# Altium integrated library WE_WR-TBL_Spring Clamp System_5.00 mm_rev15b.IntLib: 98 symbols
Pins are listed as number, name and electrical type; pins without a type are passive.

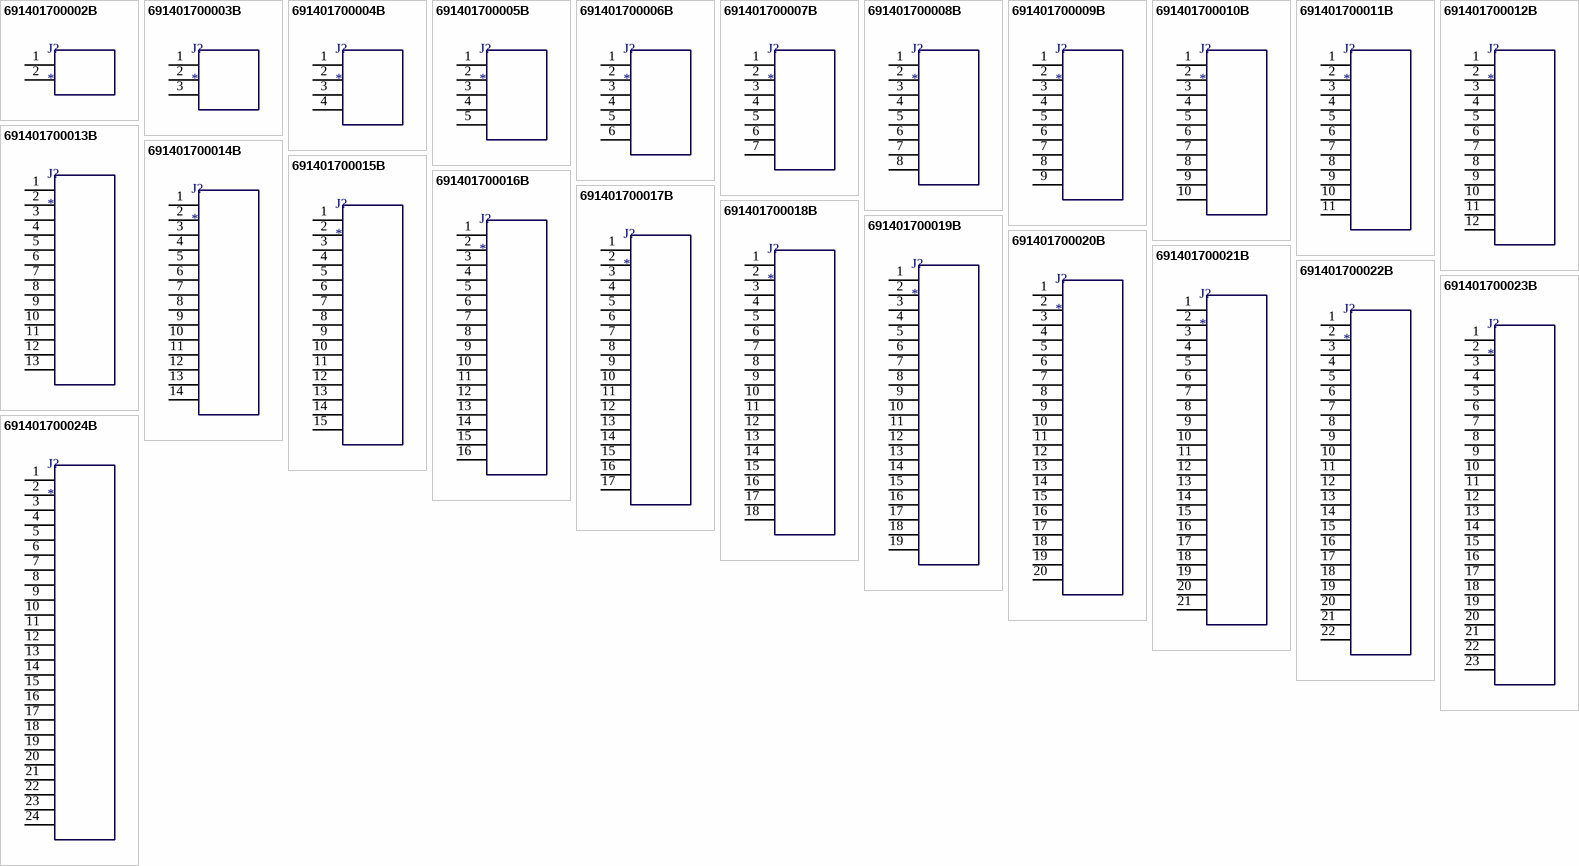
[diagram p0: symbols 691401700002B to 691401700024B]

## 691401700002B
designator J?
WR-TBL Screwless Entry Vertical,Serie 401 B - 5.00 mm; Manufacturer: Würth Elektronik eiSos GmbH; partNo: 691401700002B; ComponentLink1 Description: Manufacturer; ComponentLink2 Description: Datasheet; NoPins: 4
footprint 691401700002B
pins: 1  , 2  

## 691401700003B
designator J?
WR-TBL Screwless Entry Vertical,Serie 401 B - 5.00 mm; Manufacturer: Würth Elektronik eiSos GmbH; partNo: 691401700003B; ComponentLink1 Description: Manufacturer; ComponentLink2 Description: Datasheet; NoPins: 6
footprint 691401700003B
pins: 1  , 2  , 3  

## 691401700004B
designator J?
WR-TBL Screwless Entry Vertical,Serie 401 B - 5.00 mm; Manufacturer: Würth Elektronik eiSos GmbH; partNo: 691401700004B; ComponentLink1 Description: Manufacturer; ComponentLink2 Description: Datasheet; NoPins: 8
footprint 691401700004B
pins: 1  , 2  , 3  , 4  

## 691401700005B
designator J?
WR-TBL Screwless Entry Vertical,Serie 401 B - 5.00 mm; Manufacturer: Würth Elektronik eiSos GmbH; partNo: 691401700005B; ComponentLink1 Description: Manufacturer; ComponentLink2 Description: Datasheet; NoPins: 10
footprint 691401700005B
pins: 1  , 2  , 3  , 4  , 5  

## 691401700006B
designator J?
WR-TBL Screwless Entry Vertical,Serie 401 B - 5.00 mm; Manufacturer: Würth Elektronik eiSos GmbH; partNo: 691401700006B; ComponentLink1 Description: Manufacturer; ComponentLink2 Description: Datasheet; NoPins: 12
footprint 691401700006B
pins: 1  , 2  , 3  , 4  , 5  , 6  

## 691401700007B
designator J?
WR-TBL Screwless Entry Vertical,Serie 401 B - 5.00 mm; Manufacturer: Würth Elektronik eiSos GmbH; partNo: 691401700007B; ComponentLink1 Description: Manufacturer; ComponentLink2 Description: Datasheet; NoPins: 14
footprint 691401700007B
pins: 1  , 2  , 3  , 4  , 5  , 6  , 7  

## 691401700008B
designator J?
WR-TBL Screwless Entry Vertical,Serie 401 B - 5.00 mm; Manufacturer: Würth Elektronik eiSos GmbH; partNo: 691401700008B; ComponentLink1 Description: Manufacturer; ComponentLink2 Description: Datasheet; NoPins: 16
footprint 691401700008B
pins: 1  , 2  , 3  , 4  , 5  , 6  , 7  , 8  

## 691401700009B
designator J?
WR-TBL Screwless Entry Vertical,Serie 401 B - 5.00 mm; Manufacturer: Würth Elektronik eiSos GmbH; partNo: 691401700009B; ComponentLink1 Description: Manufacturer; ComponentLink2 Description: Datasheet; NoPins: 18
footprint 691401700009B
pins: 1  , 2  , 3  , 4  , 5  , 6  , 7  , 8  , 9  

## 691401700010B
designator J?
WR-TBL Screwless Entry Vertical,Serie 401 B - 5.00 mm; Manufacturer: Würth Elektronik eiSos GmbH; partNo: 691401700010B; ComponentLink1 Description: Manufacturer; ComponentLink2 Description: Datasheet; NoPins: 20
footprint 691401700010B
pins: 1  , 2  , 3  , 4  , 5  , 6  , 7  , 8  , 9  , 10  

## 691401700011B
designator J?
WR-TBL Screwless Entry Vertical,Serie 401 B - 5.00 mm; Manufacturer: Würth Elektronik eiSos GmbH; partNo: 691401700011B; ComponentLink1 Description: Manufacturer; ComponentLink2 Description: Datasheet; NoPins: 22
footprint 691401700011B
pins: 1  , 2  , 3  , 4  , 5  , 6  , 7  , 8  , 9  , 10  , 11  

## 691401700012B
designator J?
WR-TBL Screwless Entry Vertical,Serie 401 B - 5.00 mm; Manufacturer: Würth Elektronik eiSos GmbH; partNo: 691401700012B; ComponentLink1 Description: Manufacturer; ComponentLink2 Description: Datasheet; NoPins: 24
footprint 691401700012B
pins: 1  , 2  , 3  , 4  , 5  , 6  , 7  , 8  , 9  , 10  , 11  , 12  

## 691401700013B
designator J?
WR-TBL Screwless Entry Vertical,Serie 401 B - 5.00 mm; Manufacturer: Würth Elektronik eiSos GmbH; partNo: 691401700013B; ComponentLink1 Description: Manufacturer; ComponentLink2 Description: Datasheet; NoPins: 26
footprint 691401700013B
pins: 1  , 2  , 3  , 4  , 5  , 6  , 7  , 8  , 9  , 10  , 11  , 12  , 13  

## 691401700014B
designator J?
WR-TBL Screwless Entry Vertical,Serie 401 B - 5.00 mm; Manufacturer: Würth Elektronik eiSos GmbH; partNo: 691401700014B; ComponentLink1 Description: Manufacturer; ComponentLink2 Description: Datasheet; NoPins: 28
footprint 691401700014B
pins: 1  , 2  , 3  , 4  , 5  , 6  , 7  , 8  , 9  , 10  , 11  , 12  , 13  , 14  

## 691401700015B
designator J?
WR-TBL Screwless Entry Vertical,Serie 401 B - 5.00 mm; Manufacturer: Würth Elektronik eiSos GmbH; partNo: 691401700015B; ComponentLink1 Description: Manufacturer; ComponentLink2 Description: Datasheet; NoPins: 30
footprint 691401700015B
pins: 1  , 2  , 3  , 4  , 5  , 6  , 7  , 8  , 9  , 10  , 11  , 12  , 13  , 14  , 15  

## 691401700016B
designator J?
WR-TBL Screwless Entry Vertical,Serie 401 B - 5.00 mm; Manufacturer: Würth Elektronik eiSos GmbH; partNo: 691401700016B; ComponentLink1 Description: Manufacturer; ComponentLink2 Description: Datasheet; NoPins: 32
footprint 691401700016B
pins: 1  , 2  , 3  , 4  , 5  , 6  , 7  , 8  , 9  , 10  , 11  , 12  , 13  , 14  , 15  , 16  

## 691401700017B
designator J?
WR-TBL Screwless Entry Vertical,Serie 401 B - 5.00 mm; Manufacturer: Würth Elektronik eiSos GmbH; partNo: 691401700017B; ComponentLink1 Description: Manufacturer; ComponentLink2 Description: Datasheet; NoPins: 34
footprint 691401700017B
pins: 1  , 2  , 3  , 4  , 5  , 6  , 7  , 8  , 9  , 10  , 11  , 12  , 13  , 14  , 15  , 16  , 17  

## 691401700018B
designator J?
WR-TBL Screwless Entry Vertical,Serie 401 B - 5.00 mm; Manufacturer: Würth Elektronik eiSos GmbH; partNo: 691401700018B; ComponentLink1 Description: Manufacturer; ComponentLink2 Description: Datasheet; NoPins: 36
footprint 691401700018B
pins: 1  , 2  , 3  , 4  , 5  , 6  , 7  , 8  , 9  , 10  , 11  , 12  , 13  , 14  , 15  , 16  , 17  , 18  

## 691401700019B
designator J?
WR-TBL Screwless Entry Vertical,Serie 401 B - 5.00 mm; Manufacturer: Würth Elektronik eiSos GmbH; partNo: 691401700019B; ComponentLink1 Description: Manufacturer; ComponentLink2 Description: Datasheet; NoPins: 38
footprint 691401700019B
pins: 1  , 2  , 3  , 4  , 5  , 6  , 7  , 8  , 9  , 10  , 11  , 12  , 13  , 14  , 15  , 16  , 17  , 18  , 19  

## 691401700020B
designator J?
WR-TBL Screwless Entry Vertical,Serie 401 B - 5.00 mm; Manufacturer: Würth Elektronik eiSos GmbH; partNo: 691401700020B; ComponentLink1 Description: Manufacturer; ComponentLink2 Description: Datasheet; NoPins: 40
footprint 691401700020B
pins: 1  , 2  , 3  , 4  , 5  , 6  , 7  , 8  , 9  , 10  , 11  , 12  , 13  , 14  , 15  , 16  , 17  , 18  , 19  , 20  

## 691401700021B
designator J?
WR-TBL Screwless Entry Vertical,Serie 401 B - 5.00 mm; Manufacturer: Würth Elektronik eiSos GmbH; partNo: 691401700021B; ComponentLink1 Description: Manufacturer; ComponentLink2 Description: Datasheet; NoPins: 42
footprint 691401700021B
pins: 1  , 2  , 3  , 4  , 5  , 6  , 7  , 8  , 9  , 10  , 11  , 12  , 13  , 14  , 15  , 16  , 17  , 18  , 19  , 20  , 21  

## 691401700022B
designator J?
WR-TBL Screwless Entry Vertical,Serie 401 B - 5.00 mm; Manufacturer: Würth Elektronik eiSos GmbH; partNo: 691401700022B; ComponentLink1 Description: Manufacturer; ComponentLink2 Description: Datasheet; NoPins: 44
footprint 691401700022B
pins: 1  , 2  , 3  , 4  , 5  , 6  , 7  , 8  , 9  , 10  , 11  , 12  , 13  , 14  , 15  , 16  , 17  , 18  , 19  , 20  , 21  , 22  

## 691401700023B
designator J?
WR-TBL Screwless Entry Vertical,Serie 401 B - 5.00 mm; Manufacturer: Würth Elektronik eiSos GmbH; partNo: 691401700023B; ComponentLink1 Description: Manufacturer; ComponentLink2 Description: Datasheet; NoPins: 46
footprint 691401700023B
pins: 1  , 2  , 3  , 4  , 5  , 6  , 7  , 8  , 9  , 10  , 11  , 12  , 13  , 14  , 15  , 16  , 17  , 18  , 19  , 20  , 21  , 22  , 23  

## 691401700024B
designator J?
WR-TBL Screwless Entry Vertical,Serie 401 B - 5.00 mm; Manufacturer: Würth Elektronik eiSos GmbH; partNo: 691401700024B; ComponentLink1 Description: Manufacturer; ComponentLink2 Description: Datasheet; NoPins: 48
footprint 691401700024B
pins: 1  , 2  , 3  , 4  , 5  , 6  , 7  , 8  , 9  , 10  , 11  , 12  , 13  , 14  , 15  , 16  , 17  , 18  , 19  , 20  , 21  , 22  , 23  , 24  


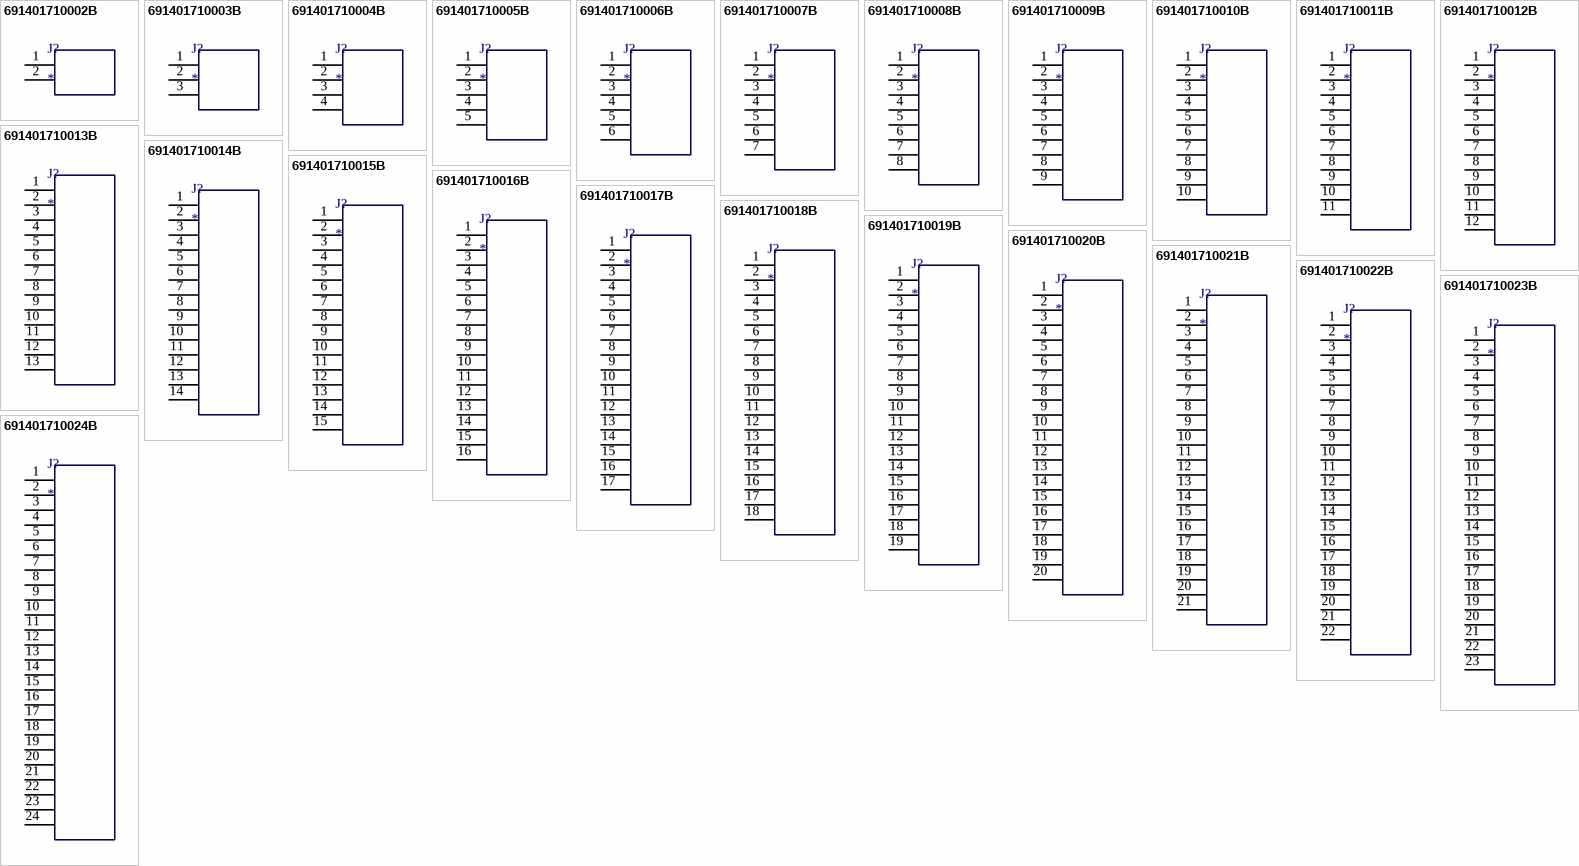
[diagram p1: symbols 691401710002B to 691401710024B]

## 691401710002B
designator J?
WR-TBL Screwless Entry Horizontal,Serie 401 B - 5.00 mm; Manufacturer: Würth Elektronik eiSos GmbH; partNo: 691401710002B; ComponentLink1 Description: Manufacturer; ComponentLink2 Description: Datasheet; NoPins: 4
footprint 691401710002B
pins: 1  , 2  

## 691401710003B
designator J?
WR-TBL Screwless Entry Horizontal,Serie 401 B - 5.00 mm; Manufacturer: Würth Elektronik eiSos GmbH; partNo: 691401710003B; ComponentLink1 Description: Manufacturer; ComponentLink2 Description: Datasheet; NoPins: 6
footprint 691401710003B
pins: 1  , 2  , 3  

## 691401710004B
designator J?
WR-TBL Screwless Entry Horizontal,Serie 401 B - 5.00 mm; Manufacturer: Würth Elektronik eiSos GmbH; partNo: 691401710004B; ComponentLink1 Description: Manufacturer; ComponentLink2 Description: Datasheet; NoPins: 8
footprint 691401710004B
pins: 1  , 2  , 3  , 4  

## 691401710005B
designator J?
WR-TBL Screwless Entry Horizontal,Serie 401 B - 5.00 mm; Manufacturer: Würth Elektronik eiSos GmbH; partNo: 691401710005B; ComponentLink1 Description: Manufacturer; ComponentLink2 Description: Datasheet; NoPins: 10
footprint 691401710005B
pins: 1  , 2  , 3  , 4  , 5  

## 691401710006B
designator J?
WR-TBL Screwless Entry Horizontal,Serie 401 B - 5.00 mm; Manufacturer: Würth Elektronik eiSos GmbH; partNo: 691401710006B; ComponentLink1 Description: Manufacturer; ComponentLink2 Description: Datasheet; NoPins: 12
footprint 691401710006B
pins: 1  , 2  , 3  , 4  , 5  , 6  

## 691401710007B
designator J?
WR-TBL Screwless Entry Horizontal,Serie 401 B - 5.00 mm; Manufacturer: Würth Elektronik eiSos GmbH; partNo: 691401710007B; ComponentLink1 Description: Manufacturer; ComponentLink2 Description: Datasheet; NoPins: 14
footprint 691401710007B
pins: 1  , 2  , 3  , 4  , 5  , 6  , 7  

## 691401710008B
designator J?
WR-TBL Screwless Entry Horizontal,Serie 401 B - 5.00 mm; Manufacturer: Würth Elektronik eiSos GmbH; partNo: 691401710008B; ComponentLink1 Description: Manufacturer; ComponentLink2 Description: Datasheet; NoPins: 16
footprint 691401710008B
pins: 1  , 2  , 3  , 4  , 5  , 6  , 7  , 8  

## 691401710009B
designator J?
WR-TBL Screwless Entry Horizontal,Serie 401 B - 5.00 mm; Manufacturer: Würth Elektronik eiSos GmbH; partNo: 691401710009B; ComponentLink1 Description: Manufacturer; ComponentLink2 Description: Datasheet; NoPins: 18
footprint 691401710009B
pins: 1  , 2  , 3  , 4  , 5  , 6  , 7  , 8  , 9  

## 691401710010B
designator J?
WR-TBL Screwless Entry Horizontal,Serie 401 B - 5.00 mm; Manufacturer: Würth Elektronik eiSos GmbH; partNo: 691401710010B; ComponentLink1 Description: Manufacturer; ComponentLink2 Description: Datasheet; NoPins: 20
footprint 691401710010B
pins: 1  , 2  , 3  , 4  , 5  , 6  , 7  , 8  , 9  , 10  

## 691401710011B
designator J?
WR-TBL Screwless Entry Horizontal,Serie 401 B - 5.00 mm; Manufacturer: Würth Elektronik eiSos GmbH; partNo: 691401710011B; ComponentLink1 Description: Manufacturer; ComponentLink2 Description: Datasheet; NoPins: 22
footprint 691401710011B
pins: 1  , 2  , 3  , 4  , 5  , 6  , 7  , 8  , 9  , 10  , 11  

## 691401710012B
designator J?
WR-TBL Screwless Entry Horizontal,Serie 401 B - 5.00 mm; Manufacturer: Würth Elektronik eiSos GmbH; partNo: 691401710012B; ComponentLink1 Description: Manufacturer; ComponentLink2 Description: Datasheet; NoPins: 24
footprint 691401710012B
pins: 1  , 2  , 3  , 4  , 5  , 6  , 7  , 8  , 9  , 10  , 11  , 12  

## 691401710013B
designator J?
WR-TBL Screwless Entry Horizontal,Serie 401 B - 5.00 mm; Manufacturer: Würth Elektronik eiSos GmbH; partNo: 691401710013B; ComponentLink1 Description: Manufacturer; ComponentLink2 Description: Datasheet; NoPins: 26
footprint 691401710013B
pins: 1  , 2  , 3  , 4  , 5  , 6  , 7  , 8  , 9  , 10  , 11  , 12  , 13  

## 691401710014B
designator J?
WR-TBL Screwless Entry Horizontal,Serie 401 B - 5.00 mm; Manufacturer: Würth Elektronik eiSos GmbH; partNo: 691401710014B; ComponentLink1 Description: Manufacturer; ComponentLink2 Description: Datasheet; NoPins: 28
footprint 691401710014B
pins: 1  , 2  , 3  , 4  , 5  , 6  , 7  , 8  , 9  , 10  , 11  , 12  , 13  , 14  

## 691401710015B
designator J?
WR-TBL Screwless Entry Horizontal,Serie 401 B - 5.00 mm; Manufacturer: Würth Elektronik eiSos GmbH; partNo: 691401710015B; ComponentLink1 Description: Manufacturer; ComponentLink2 Description: Datasheet; NoPins: 30
footprint 691401710015B
pins: 1  , 2  , 3  , 4  , 5  , 6  , 7  , 8  , 9  , 10  , 11  , 12  , 13  , 14  , 15  

## 691401710016B
designator J?
WR-TBL Screwless Entry Horizontal,Serie 401 B - 5.00 mm; Manufacturer: Würth Elektronik eiSos GmbH; partNo: 691401710016B; ComponentLink1 Description: Manufacturer; ComponentLink2 Description: Datasheet; NoPins: 32
footprint 691401710016B
pins: 1  , 2  , 3  , 4  , 5  , 6  , 7  , 8  , 9  , 10  , 11  , 12  , 13  , 14  , 15  , 16  

## 691401710017B
designator J?
WR-TBL Screwless Entry Horizontal,Serie 401 B - 5.00 mm; Manufacturer: Würth Elektronik eiSos GmbH; partNo: 691401710017B; ComponentLink1 Description: Manufacturer; ComponentLink2 Description: Datasheet; NoPins: 34
footprint 691401710017B
pins: 1  , 2  , 3  , 4  , 5  , 6  , 7  , 8  , 9  , 10  , 11  , 12  , 13  , 14  , 15  , 16  , 17  

## 691401710018B
designator J?
WR-TBL Screwless Entry Horizontal,Serie 401 B - 5.00 mm; Manufacturer: Würth Elektronik eiSos GmbH; partNo: 691401710018B; ComponentLink1 Description: Manufacturer; ComponentLink2 Description: Datasheet; NoPins: 36
footprint 691401710018B
pins: 1  , 2  , 3  , 4  , 5  , 6  , 7  , 8  , 9  , 10  , 11  , 12  , 13  , 14  , 15  , 16  , 17  , 18  

## 691401710019B
designator J?
WR-TBL Screwless Entry Horizontal,Serie 401 B - 5.00 mm; Manufacturer: Würth Elektronik eiSos GmbH; partNo: 691401710019B; ComponentLink1 Description: Manufacturer; ComponentLink2 Description: Datasheet; NoPins: 38
footprint 691401710019B
pins: 1  , 2  , 3  , 4  , 5  , 6  , 7  , 8  , 9  , 10  , 11  , 12  , 13  , 14  , 15  , 16  , 17  , 18  , 19  

## 691401710020B
designator J?
WR-TBL Screwless Entry Horizontal,Serie 401 B - 5.00 mm; Manufacturer: Würth Elektronik eiSos GmbH; partNo: 691401710020B; ComponentLink1 Description: Manufacturer; ComponentLink2 Description: Datasheet; NoPins: 40
footprint 691401710020B
pins: 1  , 2  , 3  , 4  , 5  , 6  , 7  , 8  , 9  , 10  , 11  , 12  , 13  , 14  , 15  , 16  , 17  , 18  , 19  , 20  

## 691401710021B
designator J?
WR-TBL Screwless Entry Horizontal,Serie 401 B - 5.00 mm; Manufacturer: Würth Elektronik eiSos GmbH; partNo: 691401710021B; ComponentLink1 Description: Manufacturer; ComponentLink2 Description: Datasheet; NoPins: 42
footprint 691401710021B
pins: 1  , 2  , 3  , 4  , 5  , 6  , 7  , 8  , 9  , 10  , 11  , 12  , 13  , 14  , 15  , 16  , 17  , 18  , 19  , 20  , 21  

## 691401710022B
designator J?
WR-TBL Screwless Entry Horizontal,Serie 401 B - 5.00 mm; Manufacturer: Würth Elektronik eiSos GmbH; partNo: 691401710022B; ComponentLink1 Description: Manufacturer; ComponentLink2 Description: Datasheet; NoPins: 44
footprint 691401710022B
pins: 1  , 2  , 3  , 4  , 5  , 6  , 7  , 8  , 9  , 10  , 11  , 12  , 13  , 14  , 15  , 16  , 17  , 18  , 19  , 20  , 21  , 22  

## 691401710023B
designator J?
WR-TBL Screwless Entry Horizontal,Serie 401 B - 5.00 mm; Manufacturer: Würth Elektronik eiSos GmbH; partNo: 691401710023B; ComponentLink1 Description: Manufacturer; ComponentLink2 Description: Datasheet; NoPins: 46
footprint 691401710023B
pins: 1  , 2  , 3  , 4  , 5  , 6  , 7  , 8  , 9  , 10  , 11  , 12  , 13  , 14  , 15  , 16  , 17  , 18  , 19  , 20  , 21  , 22  , 23  

## 691401710024B
designator J?
WR-TBL Screwless Entry Horizontal,Serie 401 B - 5.00 mm; Manufacturer: Würth Elektronik eiSos GmbH; partNo: 691401710024B; ComponentLink1 Description: Manufacturer; ComponentLink2 Description: Datasheet; NoPins: 48
footprint 691401710024B
pins: 1  , 2  , 3  , 4  , 5  , 6  , 7  , 8  , 9  , 10  , 11  , 12  , 13  , 14  , 15  , 16  , 17  , 18  , 19  , 20  , 21  , 22  , 23  , 24  


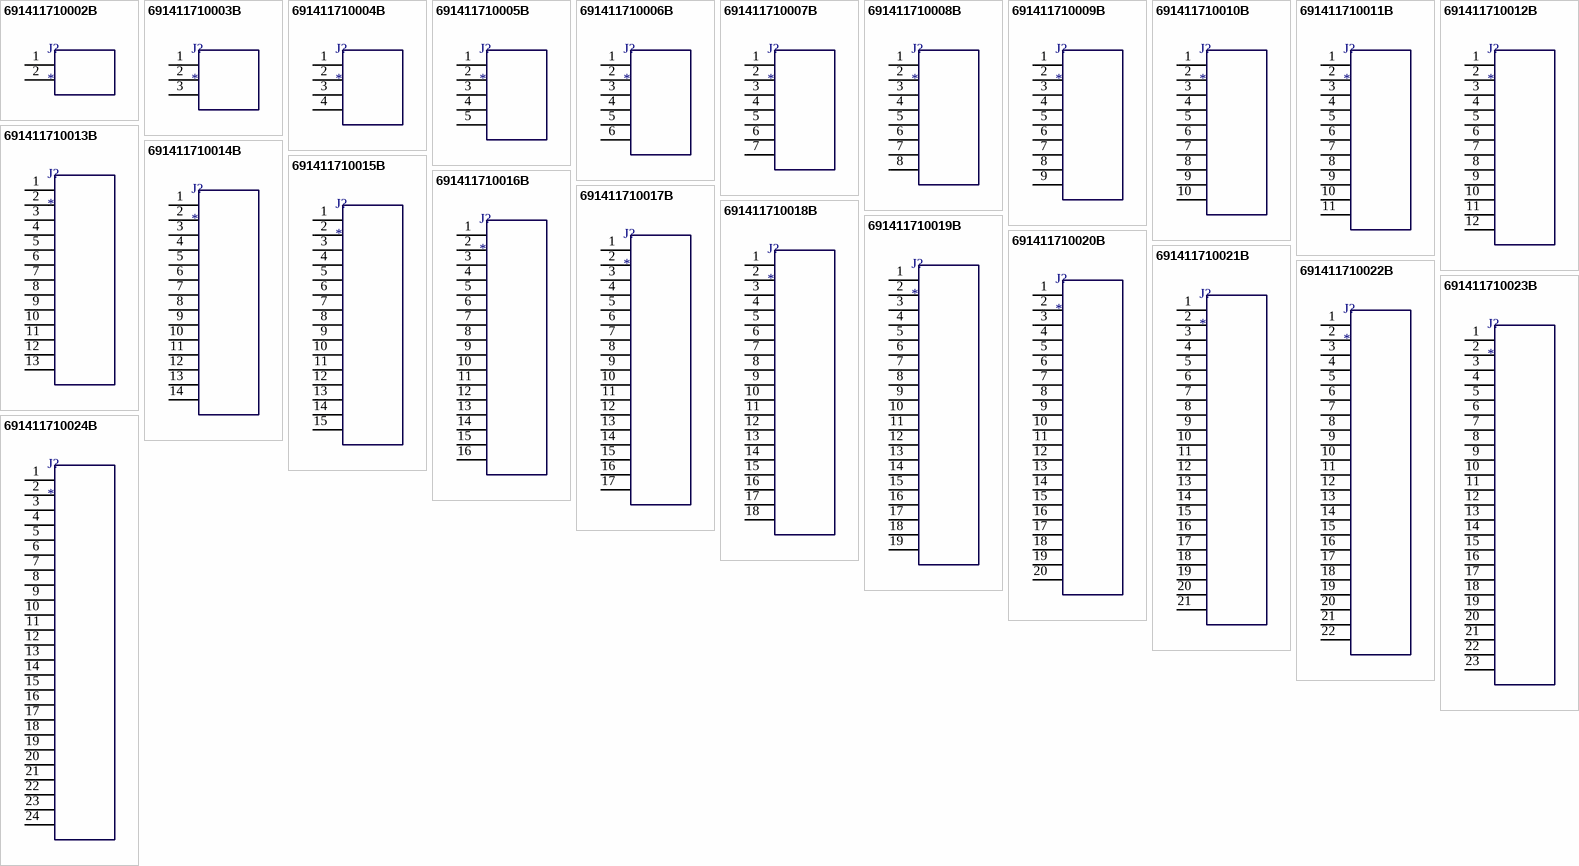
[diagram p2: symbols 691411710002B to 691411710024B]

## 691411710002B
designator J?
WR-TBL Screwless Entry Horizontal, Serie 411 B - 5.00 mm; Manufacturer: Würth Elektronik eiSos GmbH; partNo: 691411710002B; ComponentLink1 Description: Manufacturer; ComponentLink2 Description: Datasheet; NoPins: 4
footprint 691411710002B
pins: 1  , 2  

## 691411710003B
designator J?
WR-TBL Screwless Entry Horizontal, Serie 411 B - 5.00 mm; Manufacturer: Würth Elektronik eiSos GmbH; partNo: 691411710003B; ComponentLink1 Description: Manufacturer; ComponentLink2 Description: Datasheet; NoPins: 6
footprint 691411710003B
pins: 1  , 2  , 3  

## 691411710004B
designator J?
WR-TBL Screwless Entry Horizontal, Serie 411 B - 5.00 mm; Manufacturer: Würth Elektronik eiSos GmbH; partNo: 691411710004B; ComponentLink1 Description: Manufacturer; ComponentLink2 Description: Datasheet; NoPins: 8
footprint 691411710004B
pins: 1  , 2  , 3  , 4  

## 691411710005B
designator J?
WR-TBL Screwless Entry Horizontal, Serie 411 B - 5.00 mm; Manufacturer: Würth Elektronik eiSos GmbH; partNo: 691411710005B; ComponentLink1 Description: Manufacturer; ComponentLink2 Description: Datasheet; NoPins: 10
footprint 691411710005B
pins: 1  , 2  , 3  , 4  , 5  

## 691411710006B
designator J?
WR-TBL Screwless Entry Horizontal, Serie 411 B - 5.00 mm; Manufacturer: Würth Elektronik eiSos GmbH; partNo: 691411710006B; ComponentLink1 Description: Manufacturer; ComponentLink2 Description: Datasheet; NoPins: 12
footprint 691411710006B
pins: 1  , 2  , 3  , 4  , 5  , 6  

## 691411710007B
designator J?
WR-TBL Screwless Entry Horizontal, Serie 411 B - 5.00 mm; Manufacturer: Würth Elektronik eiSos GmbH; partNo: 691411710007B; ComponentLink1 Description: Manufacturer; ComponentLink2 Description: Datasheet; NoPins: 14
footprint 691411710007B
pins: 1  , 2  , 3  , 4  , 5  , 6  , 7  

## 691411710008B
designator J?
WR-TBL Screwless Entry Horizontal, Serie 411 B - 5.00 mm; Manufacturer: Würth Elektronik eiSos GmbH; partNo: 691411710008B; ComponentLink1 Description: Manufacturer; ComponentLink2 Description: Datasheet; NoPins: 16
footprint 691411710008B
pins: 1  , 2  , 3  , 4  , 5  , 6  , 7  , 8  

## 691411710009B
designator J?
WR-TBL Screwless Entry Horizontal, Serie 411 B - 5.00 mm; Manufacturer: Würth Elektronik eiSos GmbH; partNo: 691411710009B; ComponentLink1 Description: Manufacturer; ComponentLink2 Description: Datasheet; NoPins: 18
footprint 691411710009B
pins: 1  , 2  , 3  , 4  , 5  , 6  , 7  , 8  , 9  

## 691411710010B
designator J?
WR-TBL Screwless Entry Horizontal, Serie 411 B - 5.00 mm; Manufacturer: Würth Elektronik eiSos GmbH; partNo: 691411710010B; ComponentLink1 Description: Manufacturer; ComponentLink2 Description: Datasheet; NoPins: 20
footprint 691411710010B
pins: 1  , 2  , 3  , 4  , 5  , 6  , 7  , 8  , 9  , 10  

## 691411710011B
designator J?
WR-TBL Screwless Entry Horizontal, Serie 411 B - 5.00 mm; Manufacturer: Würth Elektronik eiSos GmbH; partNo: 691411710011B; ComponentLink1 Description: Manufacturer; ComponentLink2 Description: Datasheet; NoPins: 22
footprint 691411710011B
pins: 1  , 2  , 3  , 4  , 5  , 6  , 7  , 8  , 9  , 10  , 11  

## 691411710012B
designator J?
WR-TBL Screwless Entry Horizontal, Serie 411 B - 5.00 mm; Manufacturer: Würth Elektronik eiSos GmbH; partNo: 691411710012B; ComponentLink1 Description: Manufacturer; ComponentLink2 Description: Datasheet; NoPins: 24
footprint 691411710012B
pins: 1  , 2  , 3  , 4  , 5  , 6  , 7  , 8  , 9  , 10  , 11  , 12  

## 691411710013B
designator J?
WR-TBL Screwless Entry Horizontal, Serie 411 B - 5.00 mm; Manufacturer: Würth Elektronik eiSos GmbH; partNo: 691411710013B; ComponentLink1 Description: Manufacturer; ComponentLink2 Description: Datasheet; NoPins: 26
footprint 691411710013B
pins: 1  , 2  , 3  , 4  , 5  , 6  , 7  , 8  , 9  , 10  , 11  , 12  , 13  

## 691411710014B
designator J?
WR-TBL Screwless Entry Horizontal, Serie 411 B - 5.00 mm; Manufacturer: Würth Elektronik eiSos GmbH; partNo: 691411710014B; ComponentLink1 Description: Manufacturer; ComponentLink2 Description: Datasheet; NoPins: 28
footprint 691411710014B
pins: 1  , 2  , 3  , 4  , 5  , 6  , 7  , 8  , 9  , 10  , 11  , 12  , 13  , 14  

## 691411710015B
designator J?
WR-TBL Screwless Entry Horizontal, Serie 411 B - 5.00 mm; Manufacturer: Würth Elektronik eiSos GmbH; partNo: 691411710015B; ComponentLink1 Description: Manufacturer; ComponentLink2 Description: Datasheet; NoPins: 30
footprint 691411710015B
pins: 1  , 2  , 3  , 4  , 5  , 6  , 7  , 8  , 9  , 10  , 11  , 12  , 13  , 14  , 15  

## 691411710016B
designator J?
WR-TBL Screwless Entry Horizontal, Serie 411 B - 5.00 mm; Manufacturer: Würth Elektronik eiSos GmbH; partNo: 691411710016B; ComponentLink1 Description: Manufacturer; ComponentLink2 Description: Datasheet; NoPins: 32
footprint 691411710016B
pins: 1  , 2  , 3  , 4  , 5  , 6  , 7  , 8  , 9  , 10  , 11  , 12  , 13  , 14  , 15  , 16  

## 691411710017B
designator J?
WR-TBL Screwless Entry Horizontal, Serie 411 B - 5.00 mm; Manufacturer: Würth Elektronik eiSos GmbH; partNo: 691411710017B; ComponentLink1 Description: Manufacturer; ComponentLink2 Description: Datasheet; NoPins: 34
footprint 691411710017B
pins: 1  , 2  , 3  , 4  , 5  , 6  , 7  , 8  , 9  , 10  , 11  , 12  , 13  , 14  , 15  , 16  , 17  

## 691411710018B
designator J?
WR-TBL Screwless Entry Horizontal, Serie 411 B - 5.00 mm; Manufacturer: Würth Elektronik eiSos GmbH; partNo: 691411710018B; ComponentLink1 Description: Manufacturer; ComponentLink2 Description: Datasheet; NoPins: 36
footprint 691411710018B
pins: 1  , 2  , 3  , 4  , 5  , 6  , 7  , 8  , 9  , 10  , 11  , 12  , 13  , 14  , 15  , 16  , 17  , 18  

## 691411710019B
designator J?
WR-TBL Screwless Entry Horizontal, Serie 411 B - 5.00 mm; Manufacturer: Würth Elektronik eiSos GmbH; partNo: 691411710019B; ComponentLink1 Description: Manufacturer; ComponentLink2 Description: Datasheet; NoPins: 38
footprint 691411710019B
pins: 1  , 2  , 3  , 4  , 5  , 6  , 7  , 8  , 9  , 10  , 11  , 12  , 13  , 14  , 15  , 16  , 17  , 18  , 19  

## 691411710020B
designator J?
WR-TBL Screwless Entry Horizontal, Serie 411 B - 5.00 mm; Manufacturer: Würth Elektronik eiSos GmbH; partNo: 691411710020B; ComponentLink1 Description: Manufacturer; ComponentLink2 Description: Datasheet; NoPins: 40
footprint 691411710020B
pins: 1  , 2  , 3  , 4  , 5  , 6  , 7  , 8  , 9  , 10  , 11  , 12  , 13  , 14  , 15  , 16  , 17  , 18  , 19  , 20  

## 691411710021B
designator J?
WR-TBL Screwless Entry Horizontal, Serie 411 B - 5.00 mm; Manufacturer: Würth Elektronik eiSos GmbH; partNo: 691411710021B; ComponentLink1 Description: Manufacturer; ComponentLink2 Description: Datasheet; NoPins: 42
footprint 691411710021B
pins: 1  , 2  , 3  , 4  , 5  , 6  , 7  , 8  , 9  , 10  , 11  , 12  , 13  , 14  , 15  , 16  , 17  , 18  , 19  , 20  , 21  

## 691411710022B
designator J?
WR-TBL Screwless Entry Horizontal, Serie 411 B - 5.00 mm; Manufacturer: Würth Elektronik eiSos GmbH; partNo: 691411710022B; ComponentLink1 Description: Manufacturer; ComponentLink2 Description: Datasheet; NoPins: 44
footprint 691411710022B
pins: 1  , 2  , 3  , 4  , 5  , 6  , 7  , 8  , 9  , 10  , 11  , 12  , 13  , 14  , 15  , 16  , 17  , 18  , 19  , 20  , 21  , 22  

## 691411710023B
designator J?
WR-TBL Screwless Entry Horizontal, Serie 411 B - 5.00 mm; Manufacturer: Würth Elektronik eiSos GmbH; partNo: 691411710023B; ComponentLink1 Description: Manufacturer; ComponentLink2 Description: Datasheet; NoPins: 46
footprint 691411710023B
pins: 1  , 2  , 3  , 4  , 5  , 6  , 7  , 8  , 9  , 10  , 11  , 12  , 13  , 14  , 15  , 16  , 17  , 18  , 19  , 20  , 21  , 22  , 23  

## 691411710024B
designator J?
WR-TBL Screwless Entry Horizontal, Serie 411 B - 5.00 mm; Manufacturer: Würth Elektronik eiSos GmbH; partNo: 691411710024B; ComponentLink1 Description: Manufacturer; ComponentLink2 Description: Datasheet; NoPins: 48
footprint 691411710024B
pins: 1  , 2  , 3  , 4  , 5  , 6  , 7  , 8  , 9  , 10  , 11  , 12  , 13  , 14  , 15  , 16  , 17  , 18  , 19  , 20  , 21  , 22  , 23  , 24  


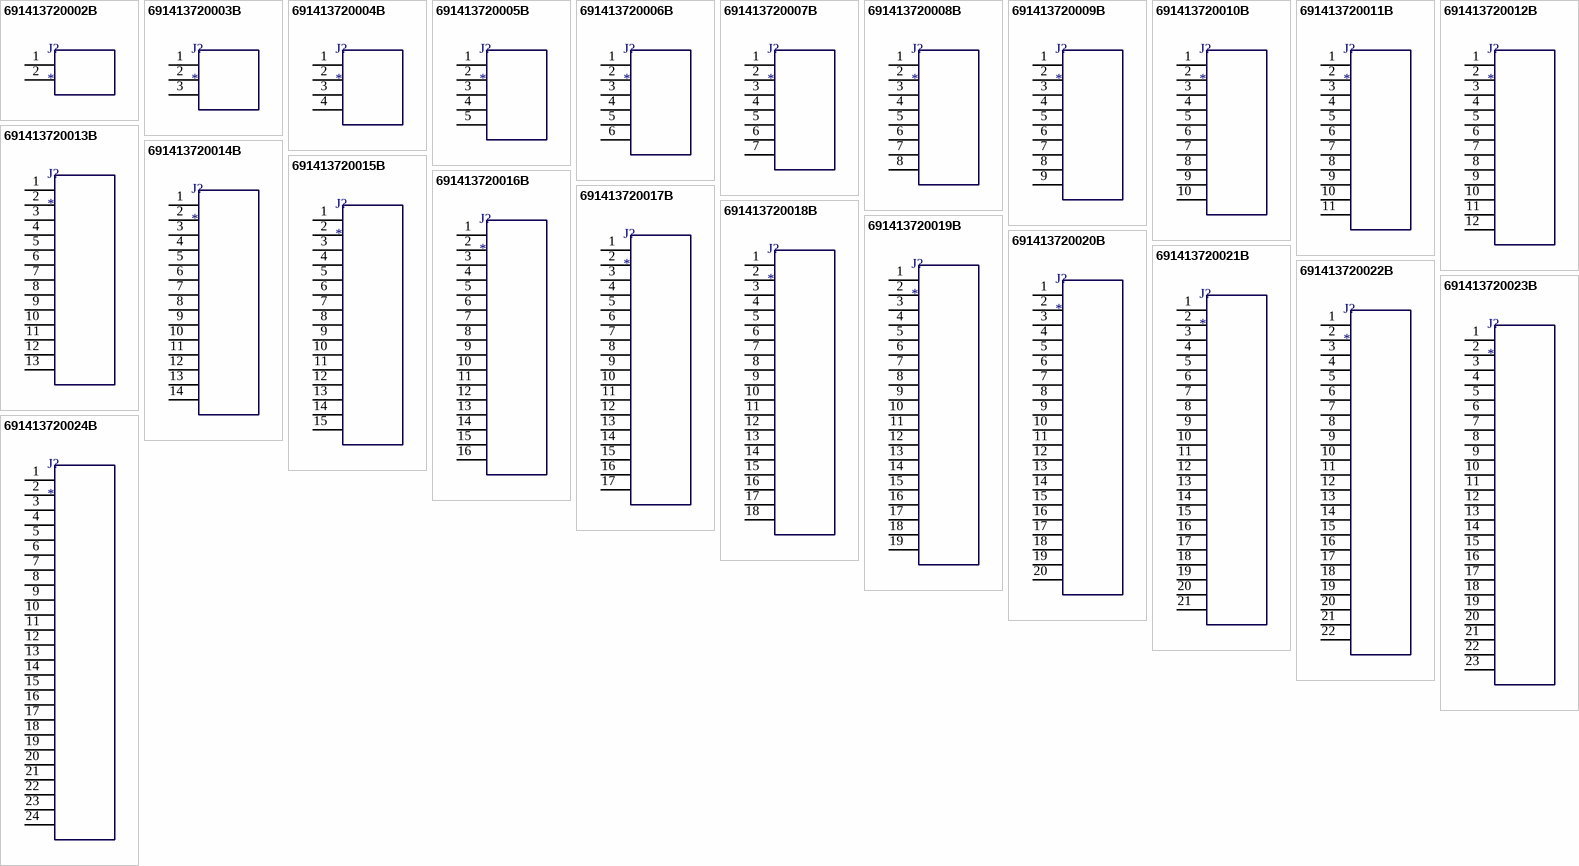
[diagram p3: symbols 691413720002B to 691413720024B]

## 691413720002B
designator J?
WR-TBL Screwless Entry 45°, Serie 413 B - 5.0 mm; Manufacturer: Würth Elektronik eiSos GmbH; partNo: 691413720002B; ComponentLink1 Description: Manufacturer; ComponentLink2 Description: Datasheet; NoPins: 4
footprint 691413720002B
pins: 1  , 2  

## 691413720003B
designator J?
WR-TBL Screwless Entry 45°, Serie 413 B - 5.0 mm; Manufacturer: Würth Elektronik eiSos GmbH; partNo: 691413720003B; ComponentLink1 Description: Manufacturer; ComponentLink2 Description: Datasheet; NoPins: 6
footprint 691413720003B
pins: 1  , 2  , 3  

## 691413720004B
designator J?
WR-TBL Screwless Entry 45°, Serie 413 B - 5.0 mm; Manufacturer: Würth Elektronik eiSos GmbH; partNo: 691413720004B; ComponentLink1 Description: Manufacturer; ComponentLink2 Description: Datasheet; NoPins: 8
footprint 691413720004B
pins: 1  , 2  , 3  , 4  

## 691413720005B
designator J?
WR-TBL Screwless Entry 45°, Serie 413 B - 5.0 mm; Manufacturer: Würth Elektronik eiSos GmbH; partNo: 691413720005B; ComponentLink1 Description: Manufacturer; ComponentLink2 Description: Datasheet; NoPins: 10
footprint 691413720005B
pins: 1  , 2  , 3  , 4  , 5  

## 691413720006B
designator J?
WR-TBL Screwless Entry 45°, Serie 413 B - 5.0 mm; Manufacturer: Würth Elektronik eiSos GmbH; partNo: 691413720006B; ComponentLink1 Description: Manufacturer; ComponentLink2 Description: Datasheet; NoPins: 12
footprint 691413720006B
pins: 1  , 2  , 3  , 4  , 5  , 6  

## 691413720007B
designator J?
WR-TBL Screwless Entry 45°, Serie 413 B - 5.0 mm; Manufacturer: Würth Elektronik eiSos GmbH; partNo: 691413720007B; ComponentLink1 Description: Manufacturer; ComponentLink2 Description: Datasheet; NoPins: 14
footprint 691413720007B
pins: 1  , 2  , 3  , 4  , 5  , 6  , 7  

## 691413720008B
designator J?
WR-TBL Screwless Entry 45°, Serie 413 B - 5.0 mm; Manufacturer: Würth Elektronik eiSos GmbH; partNo: 691413720008B; ComponentLink1 Description: Manufacturer; ComponentLink2 Description: Datasheet; NoPins: 16
footprint 691413720008B
pins: 1  , 2  , 3  , 4  , 5  , 6  , 7  , 8  

## 691413720009B
designator J?
WR-TBL Screwless Entry 45°, Serie 413 B - 5.0 mm; Manufacturer: Würth Elektronik eiSos GmbH; partNo: 691413720009B; ComponentLink1 Description: Manufacturer; ComponentLink2 Description: Datasheet; NoPins: 18
footprint 691413720009B
pins: 1  , 2  , 3  , 4  , 5  , 6  , 7  , 8  , 9  

## 691413720010B
designator J?
WR-TBL Screwless Entry 45°, Serie 413 B - 5.0 mm; Manufacturer: Würth Elektronik eiSos GmbH; partNo: 691413720010B; ComponentLink1 Description: Manufacturer; ComponentLink2 Description: Datasheet; NoPins: 20
footprint 691413720010B (5.0mm - Spring clamp/Screw less - 45° entry - 11p)
pins: 1  , 2  , 3  , 4  , 5  , 6  , 7  , 8  , 9  , 10  

## 691413720011B
designator J?
WR-TBL Screwless Entry 45°, Serie 413 B - 5.0 mm; Manufacturer: Würth Elektronik eiSos GmbH; partNo: 691413720011B; ComponentLink1 Description: Manufacturer; ComponentLink2 Description: Datasheet; NoPins: 22
footprint 691413720011B
pins: 1  , 2  , 3  , 4  , 5  , 6  , 7  , 8  , 9  , 10  , 11  

## 691413720012B
designator J?
WR-TBL Screwless Entry 45°, Serie 413 B - 5.0 mm; Manufacturer: Würth Elektronik eiSos GmbH; partNo: 691413720012B; ComponentLink1 Description: Manufacturer; ComponentLink2 Description: Datasheet; NoPins: 24
footprint 691413720012B
pins: 1  , 2  , 3  , 4  , 5  , 6  , 7  , 8  , 9  , 10  , 11  , 12  

## 691413720013B
designator J?
WR-TBL Screwless Entry 45°, Serie 413 B - 5.0 mm; Manufacturer: Würth Elektronik eiSos GmbH; partNo: 691413720013B; ComponentLink1 Description: Manufacturer; ComponentLink2 Description: Datasheet; NoPins: 26
footprint 691413720013B
pins: 1  , 2  , 3  , 4  , 5  , 6  , 7  , 8  , 9  , 10  , 11  , 12  , 13  

## 691413720014B
designator J?
WR-TBL Screwless Entry 45°, Serie 413 B - 5.0 mm; Manufacturer: Würth Elektronik eiSos GmbH; partNo: 691413720014B; ComponentLink1 Description: Manufacturer; ComponentLink2 Description: Datasheet; NoPins: 28
footprint 691413720014B
pins: 1  , 2  , 3  , 4  , 5  , 6  , 7  , 8  , 9  , 10  , 11  , 12  , 13  , 14  

## 691413720015B
designator J?
WR-TBL Screwless Entry 45°, Serie 413 B - 5.0 mm; Manufacturer: Würth Elektronik eiSos GmbH; partNo: 691413720015B; ComponentLink1 Description: Manufacturer; ComponentLink2 Description: Datasheet; NoPins: 30
footprint 691413720015B
pins: 1  , 2  , 3  , 4  , 5  , 6  , 7  , 8  , 9  , 10  , 11  , 12  , 13  , 14  , 15  

## 691413720016B
designator J?
WR-TBL Screwless Entry 45°, Serie 413 B - 5.0 mm; Manufacturer: Würth Elektronik eiSos GmbH; partNo: 691413720016B; ComponentLink1 Description: Manufacturer; ComponentLink2 Description: Datasheet; NoPins: 32
footprint 691413720016B
pins: 1  , 2  , 3  , 4  , 5  , 6  , 7  , 8  , 9  , 10  , 11  , 12  , 13  , 14  , 15  , 16  

## 691413720017B
designator J?
WR-TBL Screwless Entry 45°, Serie 413 B - 5.0 mm; Manufacturer: Würth Elektronik eiSos GmbH; partNo: 691413720017B; ComponentLink1 Description: Manufacturer; ComponentLink2 Description: Datasheet; NoPins: 34
footprint 691413720017B
pins: 1  , 2  , 3  , 4  , 5  , 6  , 7  , 8  , 9  , 10  , 11  , 12  , 13  , 14  , 15  , 16  , 17  

## 691413720018B
designator J?
WR-TBL Screwless Entry 45°, Serie 413 B - 5.0 mm; Manufacturer: Würth Elektronik eiSos GmbH; partNo: 691413720018B; ComponentLink1 Description: Manufacturer; ComponentLink2 Description: Datasheet; NoPins: 36
footprint 691413720018B
pins: 1  , 2  , 3  , 4  , 5  , 6  , 7  , 8  , 9  , 10  , 11  , 12  , 13  , 14  , 15  , 16  , 17  , 18  

## 691413720019B
designator J?
WR-TBL Screwless Entry 45°, Serie 413 B - 5.0 mm; Manufacturer: Würth Elektronik eiSos GmbH; partNo: 691413720019B; ComponentLink1 Description: Manufacturer; ComponentLink2 Description: Datasheet; NoPins: 38
footprint 691413720019B
pins: 1  , 2  , 3  , 4  , 5  , 6  , 7  , 8  , 9  , 10  , 11  , 12  , 13  , 14  , 15  , 16  , 17  , 18  , 19  

## 691413720020B
designator J?
WR-TBL Screwless Entry 45°, Serie 413 B - 5.0 mm; Manufacturer: Würth Elektronik eiSos GmbH; partNo: 691413720020B; ComponentLink1 Description: Manufacturer; ComponentLink2 Description: Datasheet; NoPins: 40
footprint 691413720020B
pins: 1  , 2  , 3  , 4  , 5  , 6  , 7  , 8  , 9  , 10  , 11  , 12  , 13  , 14  , 15  , 16  , 17  , 18  , 19  , 20  

## 691413720021B
designator J?
WR-TBL Screwless Entry 45°, Serie 413 B - 5.0 mm; Manufacturer: Würth Elektronik eiSos GmbH; partNo: 691413720021B; ComponentLink1 Description: Manufacturer; ComponentLink2 Description: Datasheet; NoPins: 42
footprint 691413720021B
pins: 1  , 2  , 3  , 4  , 5  , 6  , 7  , 8  , 9  , 10  , 11  , 12  , 13  , 14  , 15  , 16  , 17  , 18  , 19  , 20  , 21  

## 691413720022B
designator J?
WR-TBL Screwless Entry 45°, Serie 413 B - 5.0 mm; Manufacturer: Würth Elektronik eiSos GmbH; partNo: 691413720022B; ComponentLink1 Description: Manufacturer; ComponentLink2 Description: Datasheet; NoPins: 44
footprint 691413720022B
pins: 1  , 2  , 3  , 4  , 5  , 6  , 7  , 8  , 9  , 10  , 11  , 12  , 13  , 14  , 15  , 16  , 17  , 18  , 19  , 20  , 21  , 22  

## 691413720023B
designator J?
WR-TBL Screwless Entry 45°, Serie 413 B - 5.0 mm; Manufacturer: Würth Elektronik eiSos GmbH; partNo: 691413720023B; ComponentLink1 Description: Manufacturer; ComponentLink2 Description: Datasheet; NoPins: 46
footprint 691413720023B
pins: 1  , 2  , 3  , 4  , 5  , 6  , 7  , 8  , 9  , 10  , 11  , 12  , 13  , 14  , 15  , 16  , 17  , 18  , 19  , 20  , 21  , 22  , 23  

## 691413720024B
designator J?
WR-TBL Screwless Entry 45°, Serie 413 B - 5.0 mm; Manufacturer: Würth Elektronik eiSos GmbH; partNo: 691413720024B; ComponentLink1 Description: Manufacturer; ComponentLink2 Description: Datasheet; NoPins: 48
footprint 691413720024B
pins: 1  , 2  , 3  , 4  , 5  , 6  , 7  , 8  , 9  , 10  , 11  , 12  , 13  , 14  , 15  , 16  , 17  , 18  , 19  , 20  , 21  , 22  , 23  , 24  


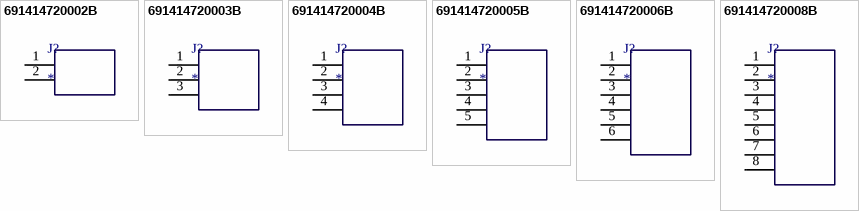
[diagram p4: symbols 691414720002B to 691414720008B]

## 691414720002B
designator J?
WR-TBL Screwless Entry 45°, Serie 4147 B - 5.00 mm; Manufacturer: Würth Elektronik eiSos GmbH; partNo: 691414720002B; ComponentLink1 Description: Manufacturer; ComponentLink2 Description: Datasheet; NoPins: 4
footprint 691414720002B
pins: 1  , 2  

## 691414720003B
designator J?
WR-TBL Screwless Entry 45°, Serie 4147 B - 5.00 mm; Manufacturer: Würth Elektronik eiSos GmbH; partNo: 691414720003B; ComponentLink1 Description: Manufacturer; ComponentLink2 Description: Datasheet; NoPins: 6
footprint 691414720003B
pins: 1  , 2  , 3  

## 691414720004B
designator J?
WR-TBL Screwless Entry 45°, Serie 4147 B - 5.00 mm; Manufacturer: Würth Elektronik eiSos GmbH; partNo: 691414720004B; ComponentLink1 Description: Manufacturer; ComponentLink2 Description: Datasheet; NoPins: 8
footprint 691414720004B
pins: 1  , 2  , 3  , 4  

## 691414720005B
designator J?
WR-TBL Screwless Entry 45°, Serie 4147 B - 5.00 mm; Manufacturer: Würth Elektronik eiSos GmbH; partNo: 691414720005B; ComponentLink1 Description: Manufacturer; ComponentLink2 Description: Datasheet; NoPins: 10
footprint 691414720005B
pins: 1  , 2  , 3  , 4  , 5  

## 691414720006B
designator J?
WR-TBL Screwless Entry 45°, Serie 4147 B - 5.00 mm; Manufacturer: Würth Elektronik eiSos GmbH; partNo: 691414720006B; ComponentLink1 Description: Manufacturer; ComponentLink2 Description: Datasheet; NoPins: 12
footprint 691414720006B
pins: 1  , 2  , 3  , 4  , 5  , 6  

## 691414720008B
designator J?
WR-TBL Screwless Entry 45°, Serie 4147 B - 5.00 mm; Manufacturer: Würth Elektronik eiSos GmbH; partNo: 691414720008B; ComponentLink1 Description: Manufacturer; ComponentLink2 Description: Datasheet; NoPins: 16
footprint 691414720008B
pins: 1  , 2  , 3  , 4  , 5  , 6  , 7  , 8  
